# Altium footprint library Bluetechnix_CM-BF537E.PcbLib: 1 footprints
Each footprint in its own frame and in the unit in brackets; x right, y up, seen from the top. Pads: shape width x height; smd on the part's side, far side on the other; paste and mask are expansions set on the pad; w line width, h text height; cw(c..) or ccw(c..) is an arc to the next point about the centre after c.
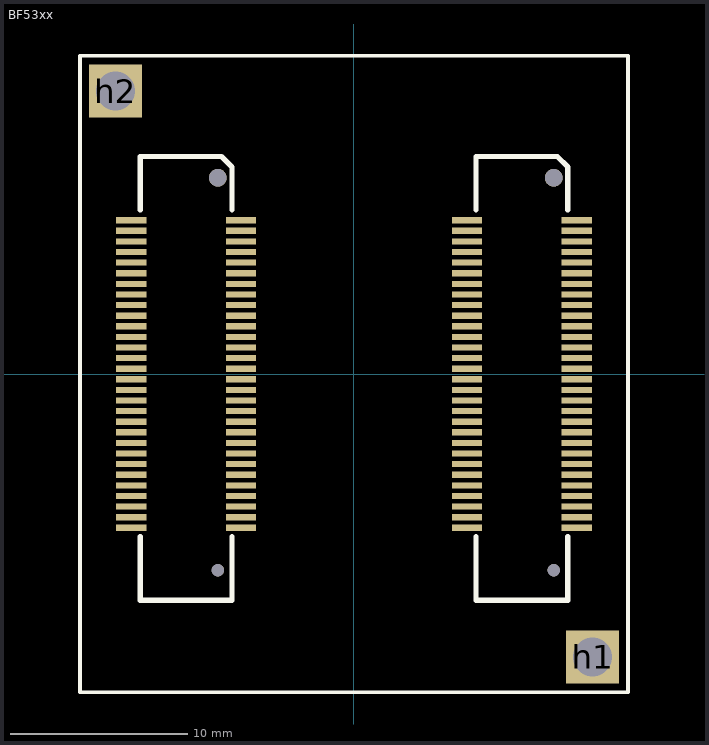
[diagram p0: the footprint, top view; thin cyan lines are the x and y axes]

## BF53xx [mm] "Blackfin Board with Harwin Connectors"
height 5
pads (126):
  rect 1.7x0.35 smd paste-0.025: 1(-6.4,8.7) 2(-6.4,8.1) 3(-6.4,7.5) 4(-6.4,6.9) 5(-6.4,6.3) 6(-6.4,5.7) 7(-6.4,5.1) 8(-6.4,4.5) 9(-6.4,3.9) 10(-6.4,3.3) 11(-6.4,2.7) 12(-6.4,2.1) 13(-6.4,1.5) 14(-6.4,0.9) 15(-6.4,0.3) 16(-6.4,-0.3) 17(-6.4,-0.9) 18(-6.4,-1.5) 19(-6.4,-2.1) 20(-6.4,-2.7) 21(-6.4,-3.3) 22(-6.4,-3.9) 23(-6.4,-4.5) 24(-6.4,-5.1) 25(-6.4,-5.7) 26(-6.4,-6.3) 27(-6.4,-6.9) 28(-6.4,-7.5) 29(-6.4,-8.1) 30(-6.4,-8.7) 31(-12.6,-8.7) 32(-12.6,-8.1) 33(-12.6,-7.5) 34(-12.6,-6.9) 35(-12.6,-6.3) 36(-12.6,-5.7) 37(-12.6,-5.1) 38(-12.6,-4.5) 39(-12.6,-3.9) 40(-12.6,-3.3) 41(-12.6,-2.7) 42(-12.6,-2.1) 43(-12.6,-1.5) 44(-12.6,-0.9) 45(-12.6,-0.3) 46(-12.6,0.3) 47(-12.6,0.9) 48(-12.6,1.5) 49(-12.6,2.1) 50(-12.6,2.7) 51(-12.6,3.3) 52(-12.6,3.9) 53(-12.6,4.5) 54(-12.6,5.1) 55(-12.6,5.7) 56(-12.6,6.3) 57(-12.6,6.9) 58(-12.6,7.5) 59(-12.6,8.1) 60(-12.6,8.7) 61(12.6,8.7) 62(12.6,8.1) 63(12.6,7.5) 64(12.6,6.9) 65(12.6,6.3) 66(12.6,5.7) 67(12.6,5.1) 68(12.6,4.5) 69(12.6,3.9) 70(12.6,3.3) 71(12.6,2.7) 72(12.6,2.1) 73(12.6,1.5) 74(12.6,0.9) 75(12.6,0.3) 76(12.6,-0.3) 77(12.6,-0.9) 78(12.6,-1.5) 79(12.6,-2.1) 80(12.6,-2.7) 81(12.6,-3.3) 82(12.6,-3.9) 83(12.6,-4.5) 84(12.6,-5.1) 85(12.6,-5.7) 86(12.6,-6.3) 87(12.6,-6.9) 88(12.6,-7.5) 89(12.6,-8.1) 90(12.6,-8.7) 91(6.4,-8.7) 92(6.4,-8.1) 93(6.4,-7.5) 94(6.4,-6.9) 95(6.4,-6.3) 96(6.4,-5.7) 97(6.4,-5.1) 98(6.4,-4.5) 99(6.4,-3.9) 100(6.4,-3.3) 101(6.4,-2.7) 102(6.4,-2.1) 103(6.4,-1.5) 104(6.4,-0.9) 105(6.4,-0.3) 106(6.4,0.3) 107(6.4,0.9) 108(6.4,1.5) 109(6.4,2.1) 110(6.4,2.7) 111(6.4,3.3) 112(6.4,3.9) 113(6.4,4.5) 114(6.4,5.1) 115(6.4,5.7) 116(6.4,6.3) 117(6.4,6.9) 118(6.4,7.5) 119(6.4,8.1) 120(6.4,8.7)
  rect 3x3 / inner rect 2.5x2.5 / far side rect 3x3 hole 2.2: h1(13.5,-16) h2(-13.5,16)
  round 1 hole 1 unplated: Hole1(-7.7,11.1) Hole1(11.3,11.1)
  round 0.7 hole 0.7 unplated: Hole2(-7.7,-11.1) Hole2(11.3,-11.1)
Top Overlay:
  lines w0.2: -15.5,-18 15.5,-18 15.5,18 -15.5,18 -15.5,-18
  lines w0.3: -12.1,-9.2 -12.1,-12.8 -6.9,-12.8 -6.9,-9.2 ; -12.1,9.3 -12.1,12.3 -7.5,12.3 -6.9,11.7 -6.9,9.3 ; 6.9,-9.2 6.9,-12.8 12.1,-12.8 12.1,-9.2 ; 6.9,9.3 6.9,12.3 11.5,12.3 12.1,11.7 12.1,9.3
